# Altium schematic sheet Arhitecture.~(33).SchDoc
size A3; SheetNumber: 1; SheetTotal: 1
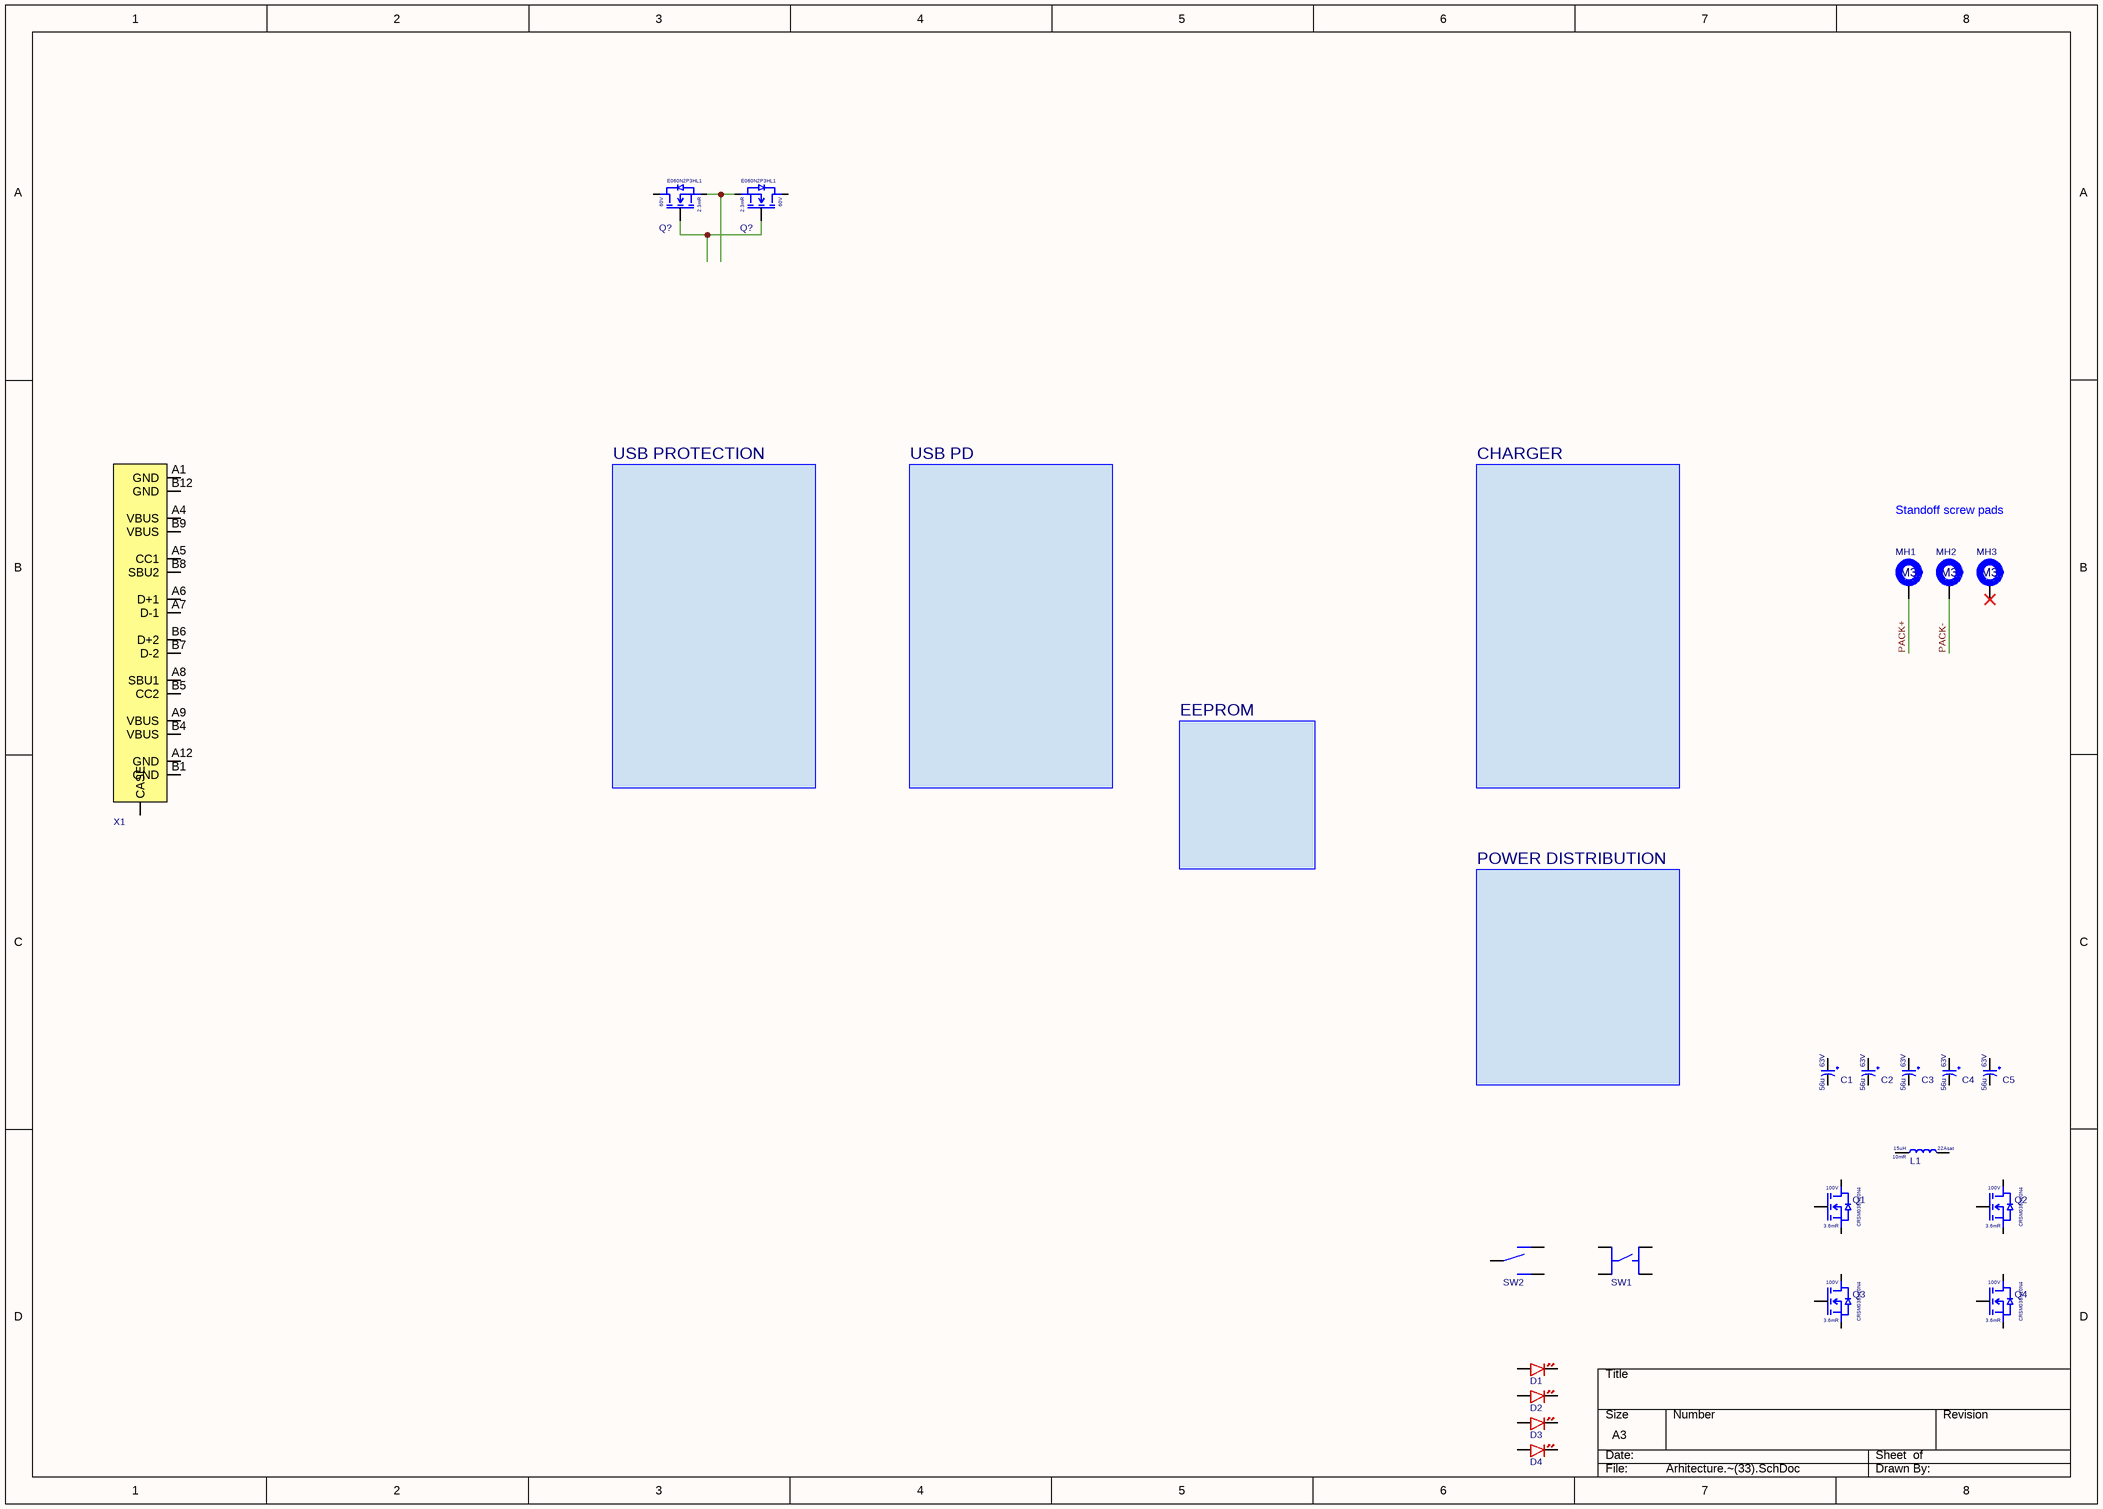
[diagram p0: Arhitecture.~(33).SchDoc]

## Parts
(Parts that share a designator on the sheet are numbered #1, #2 ... from top to bottom, then left to right.)
C1  Voltage Rating: 63V  Capacitance: 56u  [CAP_SMD_10X10.2]  (hidden comment: EEHZA1J560P)
C2  Voltage Rating: 63V  Capacitance: 56u  [CAP_SMD_10X10.2]  (hidden comment: EEHZA1J560P)
C3  Voltage Rating: 63V  Capacitance: 56u  [CAP_SMD_10X10.2]  (hidden comment: EEHZA1J560P)
C4  Voltage Rating: 63V  Capacitance: 56u  [CAP_SMD_10X10.2]  (hidden comment: EEHZA1J560P)
C5  Voltage Rating: 63V  Capacitance: 56u  [CAP_SMD_10X10.2]  (hidden comment: EEHZA1J560P)
D1  XL-1608SURC-06  [DIODE_0603]  (value not drawn)
D2  XL-1608SURC-06  [DIODE_0603]  (value not drawn)
D3  XL-1608SURC-06  [DIODE_0603]  (value not drawn)
D4  XL-1608SURC-06  [DIODE_0603]  (value not drawn)
L1  Resistance: 10mR  Saturation current: 22Asat  Inductance: 15uH  [MTF1810-150M]  (hidden comment: MTF1810-150M)
MH1  Hole size: M3  [M3 Plated]  (hidden comment: M?)  (no BOM)
MH2  Hole size: M3  [M3 Plated]  (hidden comment: M?)  (no BOM)
MH3  Hole size: M3  [M3 Plated]  (hidden comment: M?)  (no BOM)
Q1  Rds: 3.6mR  Voltage: 100V  [DFN-8 (5x6)]  (hidden comment: CRSM038N10N4)
Q2  Rds: 3.6mR  Voltage: 100V  [DFN-8 (5x6)]  (hidden comment: CRSM038N10N4)
Q3  Rds: 3.6mR  Voltage: 100V  [DFN-8 (5x6)]  (hidden comment: CRSM038N10N4)
Q4  Rds: 3.6mR  Voltage: 100V  [DFN-8 (5x6)]  (hidden comment: CRSM038N10N4)
Q?#1  Rds: 2.3mR  Voltage: 60V  [DFN-8 (5x6)]  (hidden comment: E060N2P3HL1)
Q?#2  Rds: 2.3mR  Voltage: 60V  [DFN-8 (5x6)]  (hidden comment: E060N2P3HL1)
SW1  TS4560TP  [TS4560TP]  (value not drawn)
SW2  SS-3235S-L3  [SS-3235S-L3]  (value not drawn)
X1  TYPE-C 16P LTH6.8  [TYPE-C 16P LTH6.8]  (value not drawn)

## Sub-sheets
CHARGER = Charger.SchDoc: no entries
EEPROM = EEPROM.SchDoc: no entries
POWER DISTRIBUTION = Power distribution.SchDoc: no entries
USB PD = USB PD.SchDoc: no entries
USB PROTECTION = USB protection.SchDoc: no entries

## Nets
PACK+: MH1.1
PACK-: MH2.1
NetQ?#1_G: Q?#1.G Q?#2.G
NetQ?#1_S: Q?#1.S Q?#2.S

Not connected (* = marked no-connect by the designer): C1 + -; C2 + -; C3 + -; C4 + -; C5 + -; D1 A K; D2 A K; D3 A K; D4 A K; L1 1 2; MH3 1*; Q1 D G S; Q2 D G S; Q3 D G S; Q4 D G S; Q?#1 D; Q?#2 D; SW1 1 2 3 4; SW2 1 2 3; X1 A1(GND) A4(VBUS) A5(CC1) A6(D+1) A7(D-1) A8(SBU1) A9(VBUS) A12(GND) B1(GND) B4(VBUS) B5(CC2) B6(D+2) B7(D-2) B8(SBU2) B9(VBUS) B12(GND) CASE

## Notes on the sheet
- Standoff screw pads

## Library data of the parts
C1-C5 = EEHZA1J560P: Cap AL-EL 56uF 63V 30mR 1.8Ar SMD 10x10.2mm; Manufacturer: Panasonic
D1-D4 = XL-1608SURC-06: LED Red 0603 25mA; Manufacturer: Xinglight
L1 = MTF1810-150M: Inductor 15uH 22Asat 10mR SMD 18x18x9 mm; Manufacturer: COILMX
MH1-MH3 = Mounting hole: Generic mounting hole symbol
Q1-Q4 = CRSM038N10N4: Nmos 100V 100A 3.6mR DFN-8(5x6); Manufacturer: CRMICRO
Q?#1 Q?#2 = E060N2P3HL1: Nmos 60V 180A 2.3mR PDFN5x6-8; Manufacturer: Existar
SW1 = TS4560TP: Switch Tactile SMD 4.5x4.5mm 6mmH SPST; Manufacturer: Shou Han
SW2 = SS-3235S-L3: Switch Slide SMD 9.1x3.5mm 6.6mmH; Manufacturer: XKB Connection
X1 = TYPE-C 16P LTH6.8: USB-C 16P SMD Vertical 6.50mmH; Manufacturer: Shou Han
